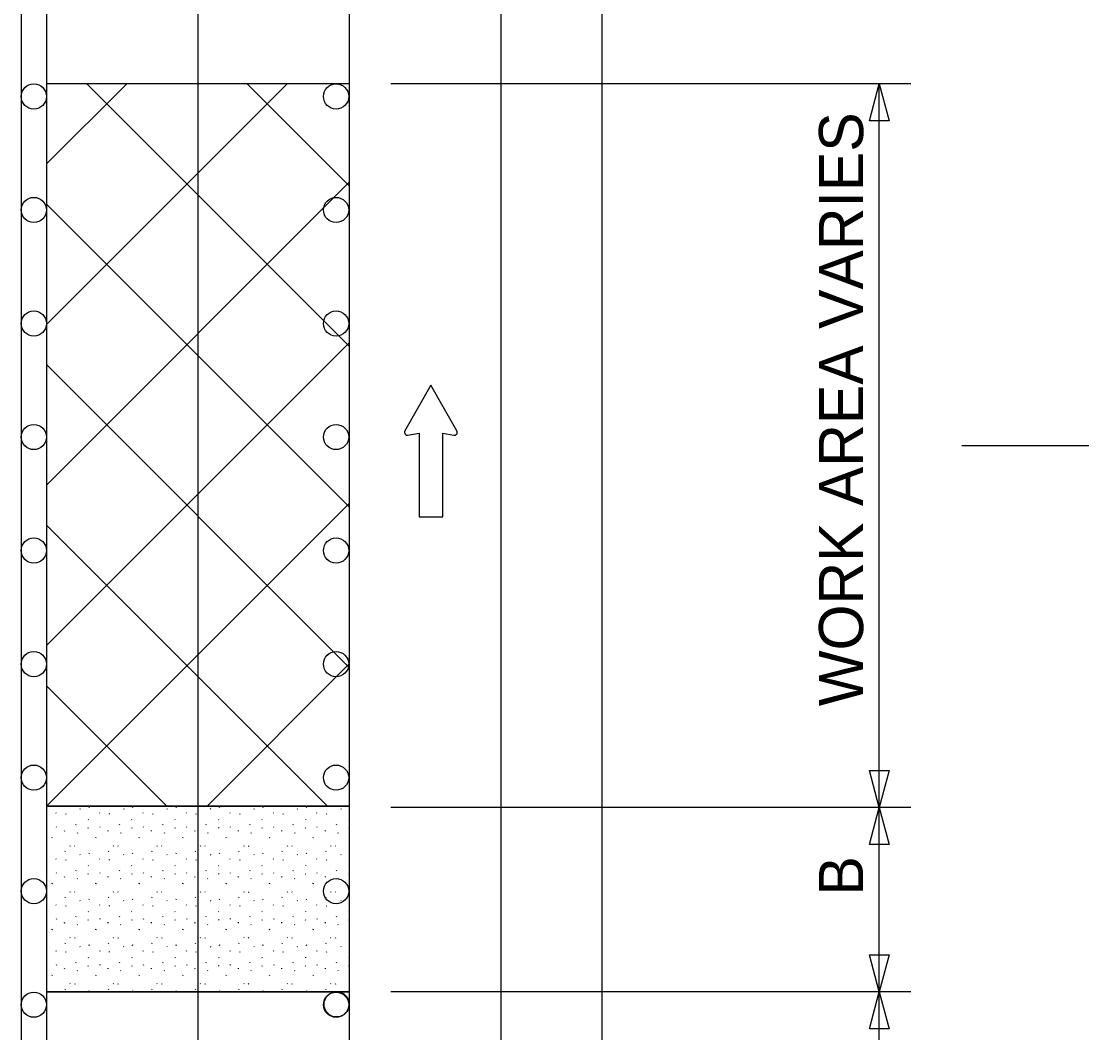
# Model space of a CAD drawing. Extents: x 16733 to 18475, y 7003 to 8205.
# Drawn here: x 16999.4 to 17167.5, y 7792.8 to 7953.1 of the extents above; entities that cross this region are included whole.
import ezdxf

# ---------------------------------------------------------------- set-up
doc = ezdxf.new("R2010")
doc.units = 0
for name, color, linetype in [('ALI_LEGAL_EX', 7, 'Continuous'), ('MT_SCRATCH_LEVEL_A', 7, 'Continuous'), ('MT_SCRATCH_LEVEL_E', 7, 'Continuous'), ('PAVT_EDGE_EX', 7, 'Continuous'), ('TRAFFIC_SIGNS_PR', 7, 'Continuous'), ('TYPICAL_TEXT_DIMEN_PR', 7, 'Continuous')]:
    doc.layers.add(name, color=color, linetype=linetype)

msp = doc.modelspace()

# ---------------------------------------------------------------- linework, layer by layer
at = {"layer": 'ALI_LEGAL_EX'}
for p, q in [((17027.37, 8191.42), (17027.37, 7362.23)), ((17051.37, 8191.42), (17051.37, 7362.23)), ((17051.37, 8191.42), (17051.37, 7362.23))]:
    msp.add_line(p, q, dxfattribs=at)
for points in [[(17027.37, 7891.42), (17027.37, 7866.42)], [(17051.37, 7891.42), (17051.37, 7866.42)]]:
    msp.add_lwpolyline(points, dxfattribs=at)
at = {"layer": 'MT_SCRATCH_LEVEL_A'}
for p, q in [((17051.37, 7943.23), (17003.37, 7943.23)), ((17051.37, 7828.69), (17003.37, 7828.69)), ((17051.37, 7799.27), (17003.37, 7799.27))]:
    msp.add_line(p, q, dxfattribs=at)
at = {"layer": 'MT_SCRATCH_LEVEL_E'}
for p, q in [((17064.29, 7895.42), (17060.18, 7888.18)), ((17064.29, 7895.42), (17060.18, 7888.18)), ((17068.43, 7888.18), (17064.29, 7895.42)), ((17068.43, 7888.18), (17064.29, 7895.42)), ((17060.66, 7887.5), (17062.43, 7887.81)), ((17060.66, 7887.5), (17062.43, 7887.81)), ((17062.43, 7887.81), (17062.43, 7874.55)), ((17062.43, 7887.81), (17062.43, 7874.55)), ((17066.18, 7874.55), (17066.18, 7887.81)), ((17066.18, 7887.81), (17067.95, 7887.5)), ((17066.18, 7874.55), (17066.18, 7887.81)), ((17066.18, 7887.81), (17067.95, 7887.5)), ((17062.43, 7874.55), (17066.18, 7874.55)), ((17062.43, 7874.55), (17066.18, 7874.55))]:
    msp.add_line(p, q, dxfattribs=at)
for centre, start, end in [((17060.58, 7887.96), 150.4248, 279.9638), ((17060.58, 7887.96), 150.4248, 279.9638), ((17068.02, 7887.96), 260.0362, 29.7731), ((17068.02, 7887.96), 260.0362, 29.7731)]:
    msp.add_arc(centre, 0.463, start, end, dxfattribs=at)
at = {"layer": 'PAVT_EDGE_EX'}
for p, q in [((16999.37, 8191.42), (16999.37, 7362.23)), ((17003.37, 8191.42), (17003.37, 7362.23)), ((17075.37, 8191.42), (17075.37, 7362.23)), ((17091.37, 8191.42), (17091.37, 7362.23)), ((17051.37, 7943.23), (17003.37, 7943.23)), ((17003.37, 7943.23), (17003.37, 7828.69)), ((17003.37, 7930.52), (17016.08, 7943.23)), ((17003.37, 7905.06), (17041.53, 7943.23)), ((17051.37, 7901.61), (17009.74, 7943.23)), ((17051.37, 7927.07), (17035.2, 7943.23)), ((17003.37, 7879.61), (17051.37, 7927.61)), ((17051.37, 7876.15), (17003.37, 7924.15)), ((17003.37, 7854.15), (17051.37, 7902.15)), ((17051.37, 7850.7), (17003.37, 7898.7)), ((17003.37, 7828.69), (17051.37, 7876.7)), ((17047.91, 7828.69), (17003.37, 7873.24)), ((17028.82, 7828.69), (17051.37, 7851.24)), ((17022.46, 7828.69), (17003.37, 7847.79)), ((17003.37, 7828.69), (17051.37, 7828.69)), ((17051.37, 7828.69), (17003.37, 7828.69)), ((17003.37, 7828.69), (17003.37, 7799.27)), ((17003.37, 7828.69), (17003.37, 7828.69)), ((17010.13, 7828.47), (17010.18, 7828.59)), ((17017.02, 7828.47), (17017.07, 7828.59)), ((17023.91, 7828.47), (17023.96, 7828.59)), ((17030.79, 7828.47), (17030.85, 7828.59)), ((17037.68, 7828.47), (17037.73, 7828.59)), ((17044.57, 7828.47), (17044.62, 7828.59)), ((17004.86, 7827.65), (17004.91, 7827.57)), ((17006.39, 7827.51), (17006.44, 7827.43)), ((17008.68, 7828.32), (17008.73, 7828.24)), ((17011.75, 7827.65), (17011.8, 7827.57)), ((17013.28, 7827.51), (17013.33, 7827.43)), ((17015.57, 7828.32), (17015.62, 7828.24)), ((17018.64, 7827.65), (17018.69, 7827.57)), ((17020.17, 7827.51), (17020.22, 7827.43)), ((17022.46, 7828.32), (17022.51, 7828.24)), ((17025.53, 7827.65), (17025.58, 7827.57)), ((17027.06, 7827.51), (17027.11, 7827.43)), ((17029.34, 7828.32), (17029.4, 7828.24)), ((17032.41, 7827.65), (17032.46, 7827.57)), ((17033.94, 7827.51), (17033.99, 7827.43)), ((17036.23, 7828.32), (17036.28, 7828.24)), ((17039.3, 7827.65), (17039.35, 7827.57)), ((17040.83, 7827.51), (17040.88, 7827.43)), ((17043.12, 7828.32), (17043.17, 7828.24)), ((17046.19, 7827.65), (17046.24, 7827.57)), ((17047.72, 7827.51), (17047.77, 7827.43)), ((17050.01, 7828.32), (17050.06, 7828.24)), ((17004.91, 7825.44), (17004.96, 7825.36)), ((17008.03, 7825.72), (17008.08, 7825.83)), ((17009.96, 7826.59), (17010.01, 7826.51)), ((17010, 7825.19), (17010.05, 7825.3)), ((17011.8, 7825.44), (17011.85, 7825.36)), ((17014.92, 7825.72), (17014.97, 7825.83)), ((17016.85, 7826.59), (17016.9, 7826.51)), ((17016.89, 7825.19), (17016.94, 7825.3)), ((17018.69, 7825.44), (17018.74, 7825.36)), ((17021.81, 7825.72), (17021.86, 7825.83)), ((17023.73, 7826.59), (17023.79, 7826.51)), ((17023.78, 7825.19), (17023.83, 7825.3)), ((17025.57, 7825.44), (17025.62, 7825.36)), ((17028.7, 7825.72), (17028.75, 7825.83)), ((17030.62, 7826.59), (17030.67, 7826.51)), ((17030.66, 7825.19), (17030.72, 7825.3)), ((17032.46, 7825.44), (17032.51, 7825.36)), ((17035.58, 7825.72), (17035.64, 7825.83)), ((17037.51, 7826.59), (17037.56, 7826.51)), ((17037.55, 7825.19), (17037.6, 7825.3)), ((17039.35, 7825.44), (17039.4, 7825.36)), ((17042.47, 7825.72), (17042.52, 7825.83)), ((17044.4, 7826.59), (17044.45, 7826.51)), ((17044.44, 7825.19), (17044.49, 7825.3)), ((17046.24, 7825.44), (17046.29, 7825.36)), ((17049.36, 7825.72), (17049.41, 7825.83)), ((17051.28, 7826.59), (17051.34, 7826.51)), ((17051.33, 7825.19), (17051.37, 7825.27)), ((17004.29, 7823.68), (17004.34, 7823.8)), ((17006.19, 7824.86), (17006.21, 7824.74)), ((17008.22, 7824.52), (17008.27, 7824.44)), ((17011.18, 7823.68), (17011.23, 7823.8)), ((17013.08, 7824.86), (17013.09, 7824.74)), ((17015.11, 7824.52), (17015.16, 7824.44)), ((17018.07, 7823.68), (17018.12, 7823.8)), ((17019.97, 7824.86), (17019.98, 7824.74)), ((17022, 7824.52), (17022.05, 7824.44)), ((17024.96, 7823.68), (17025.01, 7823.8)), ((17026.85, 7824.86), (17026.87, 7824.74)), ((17028.89, 7824.52), (17028.94, 7824.44)), ((17031.84, 7823.68), (17031.89, 7823.8)), ((17033.74, 7824.86), (17033.76, 7824.74)), ((17035.77, 7824.52), (17035.82, 7824.44)), ((17038.73, 7823.68), (17038.78, 7823.8)), ((17040.63, 7824.86), (17040.64, 7824.74)), ((17042.66, 7824.52), (17042.71, 7824.44)), ((17045.62, 7823.68), (17045.67, 7823.8)), ((17047.52, 7824.86), (17047.53, 7824.74)), ((17049.55, 7824.52), (17049.6, 7824.44)), ((17007.08, 7822.45), (17007.13, 7822.37)), ((17007.81, 7822.42), (17007.87, 7822.34)), ((17013.96, 7822.45), (17014.01, 7822.37)), ((17014.7, 7822.42), (17014.75, 7822.34)), ((17020.85, 7822.45), (17020.9, 7822.37)), ((17021.59, 7822.42), (17021.64, 7822.34)), ((17027.74, 7822.45), (17027.79, 7822.37)), ((17028.48, 7822.42), (17028.53, 7822.34)), ((17034.63, 7822.45), (17034.68, 7822.37)), ((17035.36, 7822.42), (17035.42, 7822.34)), ((17041.51, 7822.45), (17041.56, 7822.37)), ((17042.25, 7822.42), (17042.3, 7822.34)), ((17048.4, 7822.45), (17048.45, 7822.37)), ((17049.14, 7822.42), (17049.19, 7822.34)), ((17004.86, 7820.36), (17004.91, 7820.28)), ((17006.31, 7821.49), (17006.36, 7821.6)), ((17006.39, 7820.22), (17006.44, 7820.14)), ((17008.68, 7821.04), (17008.73, 7820.96)), ((17010.13, 7821.19), (17010.18, 7821.31)), ((17011.75, 7820.36), (17011.8, 7820.28)), ((17013.2, 7821.49), (17013.25, 7821.6)), ((17013.28, 7820.22), (17013.33, 7820.14)), ((17015.57, 7821.04), (17015.62, 7820.96)), ((17017.02, 7821.19), (17017.07, 7821.31)), ((17018.64, 7820.36), (17018.69, 7820.28)), ((17020.09, 7821.49), (17020.14, 7821.6)), ((17020.17, 7820.22), (17020.22, 7820.14)), ((17022.46, 7821.04), (17022.51, 7820.96)), ((17023.91, 7821.19), (17023.96, 7821.31)), ((17025.53, 7820.36), (17025.58, 7820.28)), ((17026.97, 7821.49), (17027.03, 7821.6)), ((17027.06, 7820.22), (17027.11, 7820.14)), ((17029.34, 7821.04), (17029.4, 7820.96)), ((17030.79, 7821.19), (17030.85, 7821.31)), ((17032.41, 7820.36), (17032.46, 7820.28)), ((17033.86, 7821.49), (17033.91, 7821.6)), ((17033.94, 7820.22), (17033.99, 7820.14)), ((17036.23, 7821.04), (17036.28, 7820.96)), ((17037.68, 7821.19), (17037.73, 7821.31)), ((17039.3, 7820.36), (17039.35, 7820.28)), ((17040.75, 7821.49), (17040.8, 7821.6)), ((17040.83, 7820.22), (17040.88, 7820.14)), ((17043.12, 7821.04), (17043.17, 7820.96)), ((17044.57, 7821.19), (17044.62, 7821.31)), ((17046.19, 7820.36), (17046.24, 7820.28)), ((17047.64, 7821.49), (17047.69, 7821.6)), ((17047.72, 7820.22), (17047.77, 7820.14)), ((17050.01, 7821.04), (17050.06, 7820.96)), ((17008.03, 7818.43), (17008.08, 7818.55)), ((17009.96, 7819.3), (17010.01, 7819.22)), ((17014.92, 7818.43), (17014.97, 7818.55)), ((17016.85, 7819.3), (17016.9, 7819.22)), ((17021.81, 7818.43), (17021.86, 7818.55)), ((17023.73, 7819.3), (17023.79, 7819.22)), ((17028.7, 7818.43), (17028.75, 7818.55)), ((17030.62, 7819.3), (17030.67, 7819.22)), ((17035.58, 7818.43), (17035.64, 7818.55)), ((17037.51, 7819.3), (17037.56, 7819.22)), ((17042.47, 7818.43), (17042.52, 7818.55)), ((17044.4, 7819.3), (17044.45, 7819.22)), ((17049.36, 7818.43), (17049.41, 7818.55)), ((17051.28, 7819.3), (17051.34, 7819.22)), ((17004.91, 7818.15), (17004.96, 7818.07)), ((17006.19, 7817.57), (17006.21, 7817.46)), ((17008.22, 7817.23), (17008.27, 7817.15)), ((17010, 7817.9), (17010.05, 7818.02)), ((17011.8, 7818.15), (17011.85, 7818.07)), ((17013.08, 7817.57), (17013.09, 7817.46)), ((17015.11, 7817.23), (17015.16, 7817.15)), ((17016.89, 7817.9), (17016.94, 7818.02)), ((17018.69, 7818.15), (17018.74, 7818.07)), ((17019.97, 7817.57), (17019.98, 7817.46)), ((17022, 7817.23), (17022.05, 7817.15)), ((17023.78, 7817.9), (17023.83, 7818.02)), ((17025.57, 7818.15), (17025.62, 7818.07)), ((17026.85, 7817.57), (17026.87, 7817.46)), ((17028.89, 7817.23), (17028.94, 7817.15)), ((17030.66, 7817.9), (17030.72, 7818.02)), ((17032.46, 7818.15), (17032.51, 7818.07)), ((17033.74, 7817.57), (17033.76, 7817.46)), ((17035.77, 7817.23), (17035.82, 7817.15)), ((17037.55, 7817.9), (17037.6, 7818.02)), ((17039.35, 7818.15), (17039.4, 7818.07)), ((17040.63, 7817.57), (17040.64, 7817.46)), ((17042.66, 7817.23), (17042.71, 7817.15)), ((17044.44, 7817.9), (17044.49, 7818.02)), ((17046.24, 7818.15), (17046.29, 7818.07)), ((17047.52, 7817.57), (17047.53, 7817.46)), ((17049.55, 7817.23), (17049.6, 7817.15)), ((17051.33, 7817.9), (17051.37, 7817.99)), ((17004.29, 7816.4), (17004.34, 7816.52)), ((17007.08, 7815.16), (17007.13, 7815.08)), ((17007.81, 7815.13), (17007.87, 7815.05)), ((17011.18, 7816.4), (17011.23, 7816.52)), ((17013.96, 7815.16), (17014.01, 7815.08)), ((17014.7, 7815.13), (17014.75, 7815.05)), ((17018.07, 7816.4), (17018.12, 7816.52)), ((17020.85, 7815.16), (17020.9, 7815.08)), ((17021.59, 7815.13), (17021.64, 7815.05)), ((17024.96, 7816.4), (17025.01, 7816.52)), ((17027.74, 7815.16), (17027.79, 7815.08)), ((17028.48, 7815.13), (17028.53, 7815.05)), ((17031.84, 7816.4), (17031.89, 7816.52)), ((17034.63, 7815.16), (17034.68, 7815.08)), ((17035.36, 7815.13), (17035.42, 7815.05)), ((17038.73, 7816.4), (17038.78, 7816.52)), ((17041.51, 7815.16), (17041.56, 7815.08)), ((17042.25, 7815.13), (17042.3, 7815.05)), ((17045.62, 7816.4), (17045.67, 7816.52)), ((17048.4, 7815.16), (17048.45, 7815.08)), ((17049.14, 7815.13), (17049.19, 7815.05)), ((17006.31, 7814.2), (17006.36, 7814.32)), ((17008.68, 7813.75), (17008.73, 7813.68)), ((17010.13, 7813.9), (17010.18, 7814.02)), ((17013.2, 7814.2), (17013.25, 7814.32)), ((17015.57, 7813.75), (17015.62, 7813.68)), ((17017.02, 7813.9), (17017.07, 7814.02)), ((17020.09, 7814.2), (17020.14, 7814.32)), ((17022.46, 7813.75), (17022.51, 7813.68)), ((17023.91, 7813.9), (17023.96, 7814.02)), ((17026.97, 7814.2), (17027.03, 7814.32)), ((17029.34, 7813.75), (17029.4, 7813.68)), ((17030.79, 7813.9), (17030.85, 7814.02)), ((17033.86, 7814.2), (17033.91, 7814.32)), ((17036.23, 7813.75), (17036.28, 7813.68)), ((17037.68, 7813.9), (17037.73, 7814.02)), ((17040.75, 7814.2), (17040.8, 7814.32)), ((17043.12, 7813.75), (17043.17, 7813.68)), ((17044.57, 7813.9), (17044.62, 7814.02)), ((17047.64, 7814.2), (17047.69, 7814.32)), ((17050.01, 7813.75), (17050.06, 7813.68)), ((17004.86, 7813.07), (17004.91, 7813)), ((17006.39, 7812.94), (17006.44, 7812.86)), ((17009.96, 7812.02), (17010.01, 7811.94)), ((17011.75, 7813.07), (17011.8, 7813)), ((17013.28, 7812.94), (17013.33, 7812.86)), ((17016.85, 7812.02), (17016.9, 7811.94)), ((17018.64, 7813.07), (17018.69, 7813)), ((17020.17, 7812.94), (17020.22, 7812.86)), ((17023.73, 7812.02), (17023.79, 7811.94)), ((17025.53, 7813.07), (17025.58, 7813)), ((17027.06, 7812.94), (17027.11, 7812.86)), ((17030.62, 7812.02), (17030.67, 7811.94)), ((17032.41, 7813.07), (17032.46, 7813)), ((17033.94, 7812.94), (17033.99, 7812.86)), ((17037.51, 7812.02), (17037.56, 7811.94)), ((17039.3, 7813.07), (17039.35, 7813)), ((17040.83, 7812.94), (17040.88, 7812.86)), ((17044.4, 7812.02), (17044.45, 7811.94)), ((17046.19, 7813.07), (17046.24, 7813)), ((17047.72, 7812.94), (17047.77, 7812.86)), ((17051.28, 7812.02), (17051.34, 7811.94)), ((17004.91, 7810.87), (17004.96, 7810.79)), ((17006.19, 7810.29), (17006.21, 7810.17)), ((17008.03, 7811.15), (17008.08, 7811.26)), ((17008.22, 7809.95), (17008.27, 7809.87)), ((17010, 7810.61), (17010.05, 7810.73)), ((17011.8, 7810.87), (17011.85, 7810.79)), ((17013.08, 7810.29), (17013.09, 7810.17)), ((17014.92, 7811.15), (17014.97, 7811.26)), ((17015.11, 7809.95), (17015.16, 7809.87)), ((17016.89, 7810.61), (17016.94, 7810.73)), ((17018.69, 7810.87), (17018.74, 7810.79)), ((17019.97, 7810.29), (17019.98, 7810.17)), ((17021.81, 7811.15), (17021.86, 7811.26)), ((17022, 7809.95), (17022.05, 7809.87)), ((17023.78, 7810.61), (17023.83, 7810.73)), ((17025.57, 7810.87), (17025.62, 7810.79)), ((17026.85, 7810.29), (17026.87, 7810.17)), ((17028.7, 7811.15), (17028.75, 7811.26)), ((17028.89, 7809.95), (17028.94, 7809.87)), ((17030.66, 7810.61), (17030.72, 7810.73)), ((17032.46, 7810.87), (17032.51, 7810.79)), ((17033.74, 7810.29), (17033.76, 7810.17)), ((17035.58, 7811.15), (17035.64, 7811.26)), ((17035.77, 7809.95), (17035.82, 7809.87)), ((17037.55, 7810.61), (17037.6, 7810.73)), ((17039.35, 7810.87), (17039.4, 7810.79)), ((17040.63, 7810.29), (17040.64, 7810.17)), ((17042.47, 7811.15), (17042.52, 7811.26)), ((17042.66, 7809.95), (17042.71, 7809.87)), ((17044.44, 7810.61), (17044.49, 7810.73)), ((17046.24, 7810.87), (17046.29, 7810.79)), ((17047.52, 7810.29), (17047.53, 7810.17)), ((17049.36, 7811.15), (17049.41, 7811.26)), ((17049.55, 7809.95), (17049.6, 7809.87)), ((17051.33, 7810.61), (17051.37, 7810.7)), ((17004.29, 7809.11), (17004.34, 7809.23)), ((17011.18, 7809.11), (17011.23, 7809.23)), ((17018.07, 7809.11), (17018.12, 7809.23)), ((17024.96, 7809.11), (17025.01, 7809.23)), ((17031.84, 7809.11), (17031.89, 7809.23)), ((17038.73, 7809.11), (17038.78, 7809.23)), ((17045.62, 7809.11), (17045.67, 7809.23)), ((17006.31, 7806.92), (17006.36, 7807.03)), ((17007.08, 7807.88), (17007.13, 7807.8)), ((17007.81, 7807.85), (17007.87, 7807.77)), ((17010.13, 7806.62), (17010.18, 7806.74)), ((17013.2, 7806.92), (17013.25, 7807.03)), ((17013.96, 7807.88), (17014.01, 7807.8)), ((17014.7, 7807.85), (17014.75, 7807.77)), ((17017.02, 7806.62), (17017.07, 7806.74)), ((17020.09, 7806.92), (17020.14, 7807.03)), ((17020.85, 7807.88), (17020.9, 7807.8)), ((17021.59, 7807.85), (17021.64, 7807.77)), ((17023.91, 7806.62), (17023.96, 7806.74)), ((17026.97, 7806.92), (17027.03, 7807.03)), ((17027.74, 7807.88), (17027.79, 7807.8)), ((17028.48, 7807.85), (17028.53, 7807.77)), ((17030.79, 7806.62), (17030.85, 7806.74)), ((17033.86, 7806.92), (17033.91, 7807.03)), ((17034.63, 7807.88), (17034.68, 7807.8)), ((17035.36, 7807.85), (17035.42, 7807.77)), ((17037.68, 7806.62), (17037.73, 7806.74)), ((17040.75, 7806.92), (17040.8, 7807.03)), ((17041.51, 7807.88), (17041.56, 7807.8)), ((17042.25, 7807.85), (17042.3, 7807.77)), ((17044.57, 7806.62), (17044.62, 7806.74)), ((17047.64, 7806.92), (17047.69, 7807.03)), ((17048.4, 7807.88), (17048.45, 7807.8)), ((17049.14, 7807.85), (17049.19, 7807.77)), ((17004.86, 7805.79), (17004.91, 7805.71)), ((17006.39, 7805.65), (17006.44, 7805.57)), ((17008.68, 7806.47), (17008.73, 7806.39)), ((17011.75, 7805.79), (17011.8, 7805.71)), ((17013.28, 7805.65), (17013.33, 7805.57)), ((17015.57, 7806.47), (17015.62, 7806.39)), ((17018.64, 7805.79), (17018.69, 7805.71)), ((17020.17, 7805.65), (17020.22, 7805.57)), ((17022.46, 7806.47), (17022.51, 7806.39)), ((17025.53, 7805.79), (17025.58, 7805.71)), ((17027.06, 7805.65), (17027.11, 7805.57)), ((17029.34, 7806.47), (17029.4, 7806.39)), ((17032.41, 7805.79), (17032.46, 7805.71)), ((17033.94, 7805.65), (17033.99, 7805.57)), ((17036.23, 7806.47), (17036.28, 7806.39)), ((17039.3, 7805.79), (17039.35, 7805.71)), ((17040.83, 7805.65), (17040.88, 7805.57)), ((17043.12, 7806.47), (17043.17, 7806.39)), ((17046.19, 7805.79), (17046.24, 7805.71)), ((17047.72, 7805.65), (17047.77, 7805.57)), ((17050.01, 7806.47), (17050.06, 7806.39)), ((17004.91, 7803.58), (17004.96, 7803.5)), ((17008.03, 7803.86), (17008.08, 7803.98)), ((17009.96, 7804.73), (17010.01, 7804.65)), ((17010, 7803.33), (17010.05, 7803.45)), ((17011.8, 7803.58), (17011.85, 7803.5)), ((17014.92, 7803.86), (17014.97, 7803.98)), ((17016.85, 7804.73), (17016.9, 7804.65)), ((17016.89, 7803.33), (17016.94, 7803.45)), ((17018.69, 7803.58), (17018.74, 7803.5)), ((17021.81, 7803.86), (17021.86, 7803.98)), ((17023.73, 7804.73), (17023.79, 7804.65)), ((17023.78, 7803.33), (17023.83, 7803.45)), ((17025.57, 7803.58), (17025.62, 7803.5)), ((17028.7, 7803.86), (17028.75, 7803.98)), ((17030.62, 7804.73), (17030.67, 7804.65)), ((17030.66, 7803.33), (17030.72, 7803.45)), ((17032.46, 7803.58), (17032.51, 7803.5)), ((17035.58, 7803.86), (17035.64, 7803.98)), ((17037.51, 7804.73), (17037.56, 7804.65)), ((17037.55, 7803.33), (17037.6, 7803.45)), ((17039.35, 7803.58), (17039.4, 7803.5)), ((17042.47, 7803.86), (17042.52, 7803.98)), ((17044.4, 7804.73), (17044.45, 7804.65)), ((17044.44, 7803.33), (17044.49, 7803.45)), ((17046.24, 7803.58), (17046.29, 7803.5)), ((17049.36, 7803.86), (17049.41, 7803.98)), ((17051.28, 7804.73), (17051.34, 7804.65)), ((17051.33, 7803.33), (17051.37, 7803.42)), ((17004.29, 7801.83), (17004.34, 7801.94)), ((17006.19, 7803.01), (17006.21, 7802.89)), ((17008.22, 7802.66), (17008.27, 7802.58)), ((17011.18, 7801.83), (17011.23, 7801.94)), ((17013.08, 7803.01), (17013.09, 7802.89)), ((17015.11, 7802.66), (17015.16, 7802.58)), ((17018.07, 7801.83), (17018.12, 7801.94)), ((17019.97, 7803.01), (17019.98, 7802.89)), ((17022, 7802.66), (17022.05, 7802.58)), ((17024.96, 7801.83), (17025.01, 7801.94)), ((17026.85, 7803.01), (17026.87, 7802.89)), ((17028.89, 7802.66), (17028.94, 7802.58)), ((17031.84, 7801.83), (17031.89, 7801.94)), ((17033.74, 7803.01), (17033.76, 7802.89)), ((17035.77, 7802.66), (17035.82, 7802.58)), ((17038.73, 7801.83), (17038.78, 7801.94)), ((17040.63, 7803.01), (17040.64, 7802.89)), ((17042.66, 7802.66), (17042.71, 7802.58)), ((17045.62, 7801.83), (17045.67, 7801.94)), ((17047.52, 7803.01), (17047.53, 7802.89)), ((17049.55, 7802.66), (17049.6, 7802.58)), ((17007.08, 7800.59), (17007.13, 7800.51)), ((17007.81, 7800.56), (17007.87, 7800.48)), ((17013.96, 7800.59), (17014.01, 7800.51)), ((17014.7, 7800.56), (17014.75, 7800.48)), ((17020.85, 7800.59), (17020.9, 7800.51)), ((17021.59, 7800.56), (17021.64, 7800.48)), ((17027.74, 7800.59), (17027.79, 7800.51)), ((17028.48, 7800.56), (17028.53, 7800.48)), ((17034.63, 7800.59), (17034.68, 7800.51)), ((17035.36, 7800.56), (17035.42, 7800.48)), ((17041.51, 7800.59), (17041.56, 7800.51)), ((17042.25, 7800.56), (17042.3, 7800.48)), ((17048.4, 7800.59), (17048.45, 7800.51)), ((17049.14, 7800.56), (17049.19, 7800.48)), ((17003.37, 7799.27), (17051.37, 7799.27)), ((17006.31, 7799.63), (17006.36, 7799.75)), ((17010.13, 7799.33), (17010.18, 7799.45)), ((17013.2, 7799.63), (17013.25, 7799.75)), ((17017.02, 7799.33), (17017.07, 7799.45)), ((17020.09, 7799.63), (17020.14, 7799.75)), ((17023.91, 7799.33), (17023.96, 7799.45)), ((17026.97, 7799.63), (17027.03, 7799.75)), ((17030.79, 7799.33), (17030.85, 7799.45)), ((17033.86, 7799.63), (17033.91, 7799.75)), ((17037.68, 7799.33), (17037.73, 7799.45)), ((17040.75, 7799.63), (17040.8, 7799.75)), ((17044.57, 7799.33), (17044.62, 7799.45)), ((17047.64, 7799.63), (17047.69, 7799.75))]:
    msp.add_line(p, q, dxfattribs=at)
at = {"layer": 'TRAFFIC_SIGNS_PR'}
for centre in [(17001.37, 7941.22), (17049.27, 7941.22), (17001.37, 7923.22), (17049.27, 7923.22), (17001.37, 7905.22), (17049.27, 7905.22), (17001.37, 7887.22), (17049.27, 7887.22), (17001.37, 7869.22), (17049.27, 7869.22), (17001.37, 7851.22), (17049.27, 7851.22), (17001.37, 7833.22), (17049.27, 7833.22), (17001.37, 7815.22), (17049.27, 7815.22), (17001.37, 7797.22), (17049.27, 7797.22), (17049.36, 7797.27), (17049.36, 7797.27)]:
    msp.add_circle(centre, 2, dxfattribs=at)
at = {"layer": 'TYPICAL_TEXT_DIMEN_PR'}
for p, q in [((17140.37, 7943.23), (17057.97, 7943.23)), ((17133.8, 7937.37), (17135.37, 7943.23)), ((17135.37, 7828.47), (17135.37, 7943.23)), ((17135.37, 7943.23), (17136.94, 7937.37)), ((17135.37, 7937.37), (17133.8, 7937.37)), ((17136.94, 7937.37), (17135.37, 7937.37)), ((17135.37, 7828.47), (17133.8, 7834.34)), ((17133.8, 7834.34), (17135.37, 7834.34)), ((17135.37, 7834.34), (17136.94, 7834.34)), ((17136.94, 7834.34), (17135.37, 7828.47)), ((17140.37, 7828.47), (17057.97, 7828.47)), ((17133.8, 7822.61), (17135.37, 7828.47)), ((17135.37, 7799.27), (17135.37, 7828.47)), ((17135.37, 7828.47), (17136.94, 7822.61)), ((17135.37, 7822.61), (17133.8, 7822.61)), ((17136.94, 7822.61), (17135.37, 7822.61)), ((17135.37, 7799.27), (17133.8, 7805.13)), ((17133.8, 7805.13), (17135.37, 7805.13)), ((17135.37, 7805.13), (17136.94, 7805.13)), ((17136.94, 7805.13), (17135.37, 7799.27)), ((17140.37, 7799.27), (17057.97, 7799.27)), ((17133.8, 7793.4), (17135.37, 7799.27)), ((17135.37, 7768.7), (17135.37, 7799.27)), ((17135.37, 7799.27), (17136.94, 7793.4)), ((17135.37, 7793.4), (17133.8, 7793.4)), ((17136.94, 7793.4), (17135.37, 7793.4))]:
    msp.add_line(p, q, dxfattribs=at)
msp.add_open_spline([(17259.5, 7868.68), (17213.41, 7868.68), (17213.41, 7875.95), (17238.58, 7875.95), (17238.58, 7885.85), (17188.94, 7885.85), (17148.43, 7885.85)], degree=2, dxfattribs=at)

# ---------------------------------------------------------------- texts
for s, p in [('WORK AREA VARIES', (17132.81, 7844.55)), ('B', (17132.81, 7814.53))]:
    msp.add_text(s, height=7, rotation=90, dxfattribs=at).set_placement(p)

doc.saveas('drawing.dxf')
